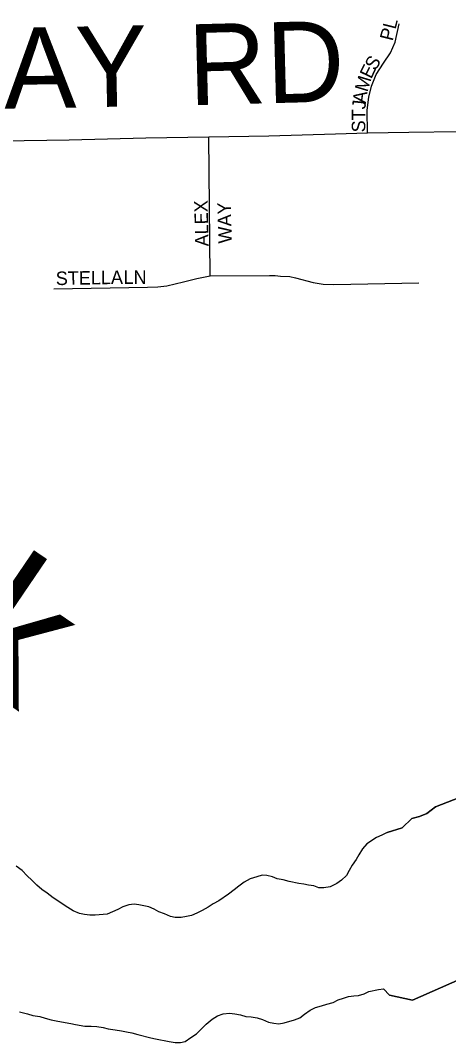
# Model space of a CAD drawing. Extents: x -10.1 to 68, y -9.5 to 29.2.
# Drawn here: x 3.183 to 3.483, y 18.251 to 18.969 of the extents above; entities that cross this region are included whole.
import ezdxf

# ---------------------------------------------------------------- set-up
doc = ezdxf.new("R2010")
doc.units = 0
for name, color, linetype in [('GM_X_Major_Lake', 7, 'Continuous'), ('GM_X_Major_River', 7, 'Continuous'), ('GM_X_Minor_River_Text', 7, 'Continuous'), ('GM_X_Township_Road', 7, 'Continuous'), ('GM_X_Township_Road_Text', 7, 'Continuous'), ('GM_X_Township_Subdivision', 7, 'Continuous'), ('GM_X_Township_Subdivision_Text', 7, 'Continuous')]:
    doc.layers.add(name, color=color, linetype=linetype)

msp = doc.modelspace()

# ---------------------------------------------------------------- linework, layer by layer
at = {"layer": 'GM_X_Major_Lake'}
for points in [[(3.49539, 18.42483), (3.47428, 18.41659), (3.46827, 18.41195), (3.46299, 18.40998), (3.4577, 18.4084), (3.45096, 18.40185), (3.44024, 18.3987)], [(3.44024, 18.3987), (3.43663, 18.39672), (3.43284, 18.39518), (3.42602, 18.3906), (3.42299, 18.38717), (3.42034, 18.38298), (3.41845, 18.37955), (3.41581, 18.37574), (3.41354, 18.37193), (3.41165, 18.3685), (3.40825, 18.36507), (3.40484, 18.36278), (3.40029, 18.36048), (3.39573, 18.35971), (3.39231, 18.3597), (3.38889, 18.36121), (3.3851, 18.36157), (3.38167, 18.36232), (3.37826, 18.36269), (3.37142, 18.36419), (3.36724, 18.36532), (3.36306, 18.36606), (3.35963, 18.36757), (3.35584, 18.36832), (3.35242, 18.36869), (3.34862, 18.36754), (3.34407, 18.366), (3.3399, 18.36371), (3.33611, 18.36103), (3.3327, 18.35836), (3.32892, 18.35531), (3.3221, 18.35072), (3.31793, 18.34843), (3.31452, 18.34614), (3.31035, 18.34384), (3.30655, 18.34193), (3.30276, 18.3404), (3.29935, 18.33963), (3.29555, 18.33885), (3.29138, 18.33884), (3.28795, 18.33959), (3.28377, 18.34148), (3.27997, 18.34299), (3.27655, 18.34487), (3.27274, 18.34638), (3.26591, 18.34788), (3.26249, 18.34825), (3.25869, 18.34786), (3.25452, 18.34632), (3.25111, 18.34441), (3.24352, 18.34135), (3.23517, 18.34056), (3.23138, 18.34054), (3.22758, 18.34091), (3.22416, 18.34166), (3.2196, 18.34355), (3.21579, 18.34582), (3.20552, 18.35263), (3.20133, 18.35604), (3.19753, 18.35868), (3.1941, 18.36171), (3.19067, 18.36512), (3.18724, 18.36815), (3.18381, 18.37194), (3.17963, 18.37497)], [(3.44186, 18.28437), (3.45807, 18.28071), (3.49161, 18.29558)], [(3.20426, 18.26709), (3.20768, 18.26634), (3.21414, 18.26522), (3.21794, 18.26447), (3.22135, 18.26372), (3.22781, 18.2626), (3.23237, 18.26262), (3.23617, 18.26225), (3.24073, 18.2615), (3.24415, 18.26075), (3.24909, 18.26001), (3.25364, 18.25926), (3.25706, 18.25851), (3.26086, 18.25777), (3.26504, 18.25664), (3.27416, 18.25439), (3.27758, 18.25364), (3.28708, 18.25177), (3.29126, 18.25102), (3.29506, 18.25104), (3.29847, 18.25181), (3.30226, 18.25448), (3.30643, 18.25715), (3.31324, 18.26402), (3.31741, 18.26745), (3.3212, 18.26975), (3.32499, 18.27128), (3.32955, 18.27168), (3.33335, 18.27131), (3.33715, 18.27056), (3.34095, 18.26943), (3.34475, 18.26906), (3.34892, 18.26832), (3.35272, 18.26719), (3.35691, 18.2653), (3.36071, 18.26455), (3.36413, 18.26419), (3.36792, 18.26496), (3.37513, 18.26688), (3.37892, 18.26842), (3.38233, 18.27109), (3.38612, 18.27376), (3.38991, 18.27567), (3.39408, 18.27683), (3.39788, 18.27798), (3.40243, 18.27914), (3.40584, 18.28105), (3.40963, 18.2822), (3.41305, 18.28335), (3.41685, 18.28375), (3.42026, 18.28414), (3.42406, 18.28529), (3.42747, 18.28682), (3.4343, 18.28836), (3.43771, 18.28876), (3.44186, 18.28437)], [(3.18184, 18.27272), (3.18754, 18.27122), (3.19134, 18.27009), (3.19628, 18.26934), (3.20008, 18.26821), (3.20426, 18.26709)]]:
    msp.add_lwpolyline(points, dxfattribs=at)
at = {"layer": 'GM_X_Major_River'}
for points in [[(3.44024, 18.3987), (3.45096, 18.40185), (3.4577, 18.4084), (3.46299, 18.40998), (3.46827, 18.41195), (3.47428, 18.41659), (3.49539, 18.42483)], [(3.44024, 18.3987), (3.43663, 18.39672), (3.43284, 18.39518), (3.42602, 18.3906), (3.42299, 18.38717), (3.42034, 18.38298), (3.41845, 18.37955), (3.41581, 18.37574), (3.41354, 18.37193), (3.41165, 18.3685), (3.40825, 18.36507), (3.40484, 18.36278), (3.40029, 18.36048), (3.39573, 18.35971), (3.39231, 18.3597), (3.38889, 18.36121), (3.3851, 18.36157), (3.38167, 18.36232), (3.37826, 18.36269), (3.37142, 18.36419), (3.36724, 18.36532), (3.36306, 18.36606), (3.35963, 18.36757), (3.35584, 18.36832), (3.35242, 18.36869), (3.34862, 18.36754), (3.34407, 18.366), (3.3399, 18.36371), (3.33611, 18.36103), (3.3327, 18.35836), (3.32892, 18.35531), (3.3221, 18.35072), (3.31793, 18.34843), (3.31452, 18.34614), (3.31035, 18.34384), (3.30655, 18.34193), (3.30276, 18.3404), (3.29935, 18.33963), (3.29555, 18.33885), (3.29138, 18.33884), (3.28795, 18.33959), (3.28377, 18.34148), (3.27997, 18.34299), (3.27655, 18.34487), (3.27274, 18.34638), (3.26591, 18.34788), (3.26249, 18.34825), (3.25869, 18.34786), (3.25452, 18.34632), (3.25111, 18.34441), (3.24352, 18.34135), (3.23517, 18.34056), (3.23138, 18.34054), (3.22758, 18.34091), (3.22416, 18.34166), (3.2196, 18.34355), (3.21579, 18.34582), (3.20552, 18.35263), (3.20133, 18.35604), (3.19753, 18.35868), (3.1941, 18.36171), (3.19067, 18.36512), (3.18724, 18.36815), (3.18381, 18.37194), (3.17963, 18.37497)], [(3.49161, 18.29558), (3.45807, 18.28071), (3.44186, 18.28437)], [(3.20426, 18.26709), (3.20768, 18.26634), (3.21414, 18.26522), (3.21794, 18.26447), (3.22135, 18.26372), (3.22781, 18.2626), (3.23237, 18.26262), (3.23617, 18.26225), (3.24073, 18.2615), (3.24415, 18.26075), (3.24909, 18.26001), (3.25364, 18.25926), (3.25706, 18.25851), (3.26086, 18.25777), (3.26504, 18.25664), (3.27416, 18.25439), (3.27758, 18.25364), (3.28708, 18.25177), (3.29126, 18.25102), (3.29506, 18.25104), (3.29847, 18.25181), (3.30226, 18.25448), (3.30643, 18.25715), (3.31324, 18.26402), (3.31741, 18.26745), (3.3212, 18.26975), (3.32499, 18.27128), (3.32955, 18.27168), (3.33335, 18.27131), (3.33715, 18.27056), (3.34095, 18.26943), (3.34475, 18.26906), (3.34892, 18.26832), (3.35272, 18.26719), (3.35691, 18.2653), (3.36071, 18.26455), (3.36413, 18.26419), (3.36792, 18.26496), (3.37513, 18.26688), (3.37892, 18.26842), (3.38233, 18.27109), (3.38612, 18.27376), (3.38991, 18.27567), (3.39408, 18.27683), (3.39788, 18.27798), (3.40243, 18.27914), (3.40584, 18.28105), (3.40963, 18.2822), (3.41305, 18.28335), (3.41685, 18.28375), (3.42026, 18.28414), (3.42406, 18.28529), (3.42747, 18.28682), (3.4343, 18.28836), (3.43771, 18.28876), (3.44186, 18.28437)], [(3.18184, 18.27272), (3.18754, 18.27122), (3.19134, 18.27009), (3.19628, 18.26934), (3.20008, 18.26821), (3.20426, 18.26709)]]:
    msp.add_lwpolyline(points, dxfattribs=at)
at = {"layer": 'GM_X_Township_Road'}
msp.add_lwpolyline([(2.70585, 18.87803), (2.75867, 18.87913), (2.81708, 18.87964), (2.92838, 18.88171), (2.99556, 18.8828), (3.0994, 18.88346), (3.16942, 18.88477), (3.21675, 18.88542), (3.27063, 18.88673), (3.31491, 18.8876), (3.35723, 18.88826), (3.40391, 18.88957), (3.42659, 18.89022), (3.45561, 18.89088), (3.49094, 18.89131)], dxfattribs=at)
at = {"layer": 'GM_X_Township_Subdivision'}
for points in [[(3.42659, 18.89022), (3.42638, 18.90615), (3.42747, 18.91531), (3.42921, 18.92316), (3.4327, 18.93123), (3.43772, 18.9393), (3.44274, 18.9465), (3.44601, 18.95392), (3.44884, 18.967)], [(3.316, 18.78988), (3.31491, 18.8876)], [(3.20606, 18.78061), (3.272, 18.78176), (3.27914, 18.78203), (3.28546, 18.78268), (3.29724, 18.78552), (3.30662, 18.78792), (3.316, 18.78988), (3.35764, 18.79003), (3.36151, 18.78996), (3.36547, 18.78962), (3.37184, 18.78923), (3.37599, 18.78835), (3.38842, 18.78508), (3.3954, 18.78399), (3.40282, 18.78377), (3.46259, 18.78486)]]:
    msp.add_lwpolyline(points, dxfattribs=at)

# ---------------------------------------------------------------- texts
at = {"layer": 'GM_X_Minor_River_Text'}
msp.add_text('Creek', height=0.094754, rotation=325.79796, dxfattribs=at).set_placement((2.90178, 18.67365))
at = {"layer": 'GM_X_Township_Road_Text'}
for s, height, rotation, p in [('A', 0.05682, 0.88886, (3.17136, 18.90729)), ('Y', 0.05682, 1.24308, (3.22174, 18.90807)), ('RD', 0.056818, 1.48251, (3.30114, 18.90964))]:
    msp.add_text(s, height=height, rotation=rotation, dxfattribs=at).set_placement(p)
at = {"layer": 'GM_X_Township_Subdivision_Text'}
for s, rotation, p in [('PL', 75.95732, (3.44416, 18.95441)), ('S', 57.62101, (3.43189, 18.9335)), ('E', 64.27818, (3.42914, 18.92775)), ('M', 73.28156, (3.42641, 18.91854)), ('A', 82.15116, (3.42535, 18.91066)), ('J', 84.2198, (3.42494, 18.90661)), ('ST', 90, (3.42494, 18.89064)), ('ALEX', 91.54737, (3.31494, 18.81059)), ('WAY', 91.73471, (3.33122, 18.81274)), ('STELLA', 1.10114, (3.20752, 18.78326)), ('LN', 0.00001, (3.25505, 18.78409))]:
    msp.add_text(s, height=0.00947, rotation=rotation, dxfattribs=at).set_placement(p)

doc.saveas('drawing.dxf')
